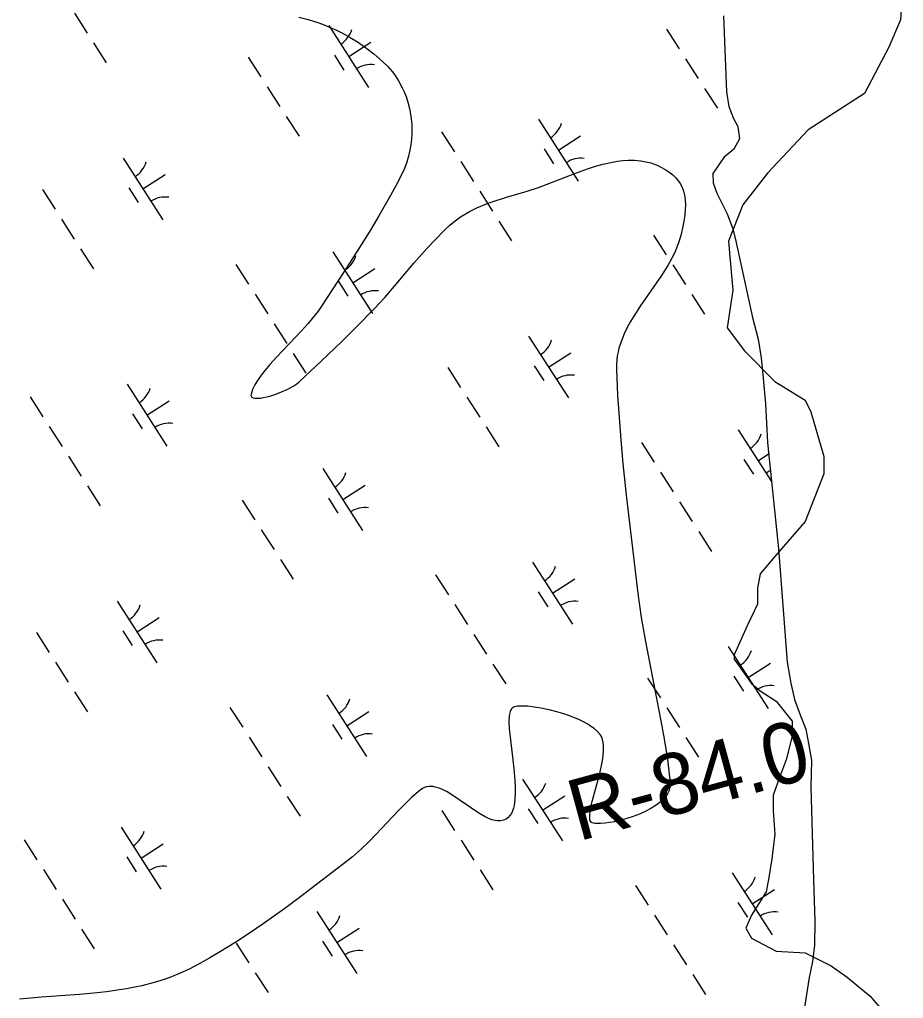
# Model space of a CAD drawing. Extents: x 3937982 to 3958556, y 219448 to 241894.
# Drawn here: x 3947210 to 3947811, y 231382 to 232047 of the extents above; entities that cross this region are included whole.
import ezdxf

# ---------------------------------------------------------------- set-up
doc = ezdxf.new("R2010")
doc.units = 0
for name, color, linetype in [('V-RIVR-EDGE', 7, 'Continuous'), ('V-RIVR-RANG-IDEN', 7, 'Continuous'), ('V-SITE-VEGE', 7, 'Continuous'), ('V-WETL-SWMP', 7, 'Continuous')]:
    doc.layers.add(name, color=color, linetype=linetype)

msp = doc.modelspace()

# ---------------------------------------------------------------- linework, layer by layer
at = {"layer": 'V-RIVR-EDGE'}
msp.add_lwpolyline([(3947811.4, 232077.583), (3947809.434, 232047.114), (3947801.571, 232028.439), (3947784.862, 231996.986), (3947746.529, 231972.413), (3947732.768, 231957.67), (3947719.008, 231942.927), (3947702.298, 231921.303), (3947692.469, 231896.73), (3947693.452, 231885.919), (3947695.418, 231863.312), (3947691.486, 231837.757), (3947703.281, 231822.03), (3947723.922, 231801.39), (3947744.563, 231788.612), (3947748.494, 231780.749), (3947757.34, 231750.279), (3947757.34, 231738.484), (3947744.563, 231706.049), (3947723.922, 231682.459), (3947714.093, 231670.664), (3947712.127, 231660.835), (3947712.127, 231650.024), (3947705.247, 231635.28), (3947696.401, 231615.622), (3947696.401, 231612.674), (3947708.196, 231595.964), (3947714.093, 231591.05), (3947724.905, 231584.17), (3947735.717, 231570.409), (3947735.717, 231560.58), (3947731.785, 231544.854), (3947727.854, 231534.042), (3947722.939, 231520.281), (3947722.939, 231509.47), (3947723.922, 231493.743), (3947721.956, 231477.034), (3947719.99, 231464.256), (3947718.025, 231454.427), (3947708.196, 231438.701), (3947704.264, 231429.855), (3947708.196, 231422.975), (3947724.905, 231414.129), (3947744.563, 231413.146), (3947762.255, 231404.3), (3947773.067, 231396.436), (3947788.793, 231383.659), (3947800.588, 231369.898)], dxfattribs=at)
at = {"layer": 'V-SITE-VEGE'}
for points in [[(3947400.382, 232048.852), (3947406.686, 232047.191), (3947413.833, 232044.926), (3947417.62, 232043.541), (3947421.638, 232041.921), (3947425.904, 232040.017), (3947430.428, 232037.776), (3947435.225, 232035.132), (3947440.306, 232032.005), (3947445.688, 232028.304), (3947451.381, 232023.913), (3947457.304, 232018.783), (3947460.778, 232015.33), (3947463.897, 232011.689), (3947465.777, 232009.17), (3947468.046, 232005.706), (3947470.655, 232000.928), (3947471.939, 231998.129), (3947473.225, 231994.873), (3947474.462, 231991.096), (3947475.581, 231986.721), (3947476.484, 231981.673), (3947477.039, 231975.877), (3947477.135, 231972.791), (3947477.086, 231969.512), (3947476.869, 231966.041), (3947476.453, 231962.377), (3947475.802, 231958.531), (3947474.882, 231954.511), (3947473.657, 231950.343), (3947472.074, 231946.054), (3947470.092, 231941.692), (3947466.479, 231934.684), (3947462.715, 231927.698), (3947454.787, 231913.786), (3947449.254, 231904.552), (3947441.641, 231892.28), (3947431.211, 231875.98), (3947415.371, 231851.74), (3947413.491, 231849.157), (3947409.399, 231843.994), (3947406.471, 231840.564), (3947402.387, 231836.011), (3947385.114, 231817.768), (3947380.674, 231812.875), (3947376.277, 231807.642), (3947374.141, 231804.845), (3947372.128, 231801.932), (3947370.32, 231798.91), (3947368.827, 231795.793), (3947368.249, 231794.23), (3947367.796, 231792.649), (3947367.745, 231791.703), (3947368.063, 231790.963), (3947368.464, 231790.582), (3947369.22, 231790.204), (3947370.576, 231789.921), (3947371.511, 231789.862), (3947374.223, 231790.03), (3947376.121, 231790.324), (3947378.462, 231790.824), (3947381.305, 231791.586), (3947384.674, 231792.676), (3947388.549, 231794.156), (3947392.8, 231796.098), (3947394.908, 231797.21), (3947396.98, 231798.437), (3947398.938, 231799.774), (3947400.677, 231801.216), (3947415.23, 231814.894), (3947429.732, 231828.772), (3947439.294, 231838.162), (3947451.826, 231850.896), (3947458.773, 231858.406), (3947465.463, 231866.082), (3947478.595, 231881.62), (3947487.586, 231891.895), (3947492.954, 231897.652), (3947499.384, 231904.083), (3947502.971, 231907.429), (3947506.548, 231910.438), (3947510.294, 231913.137), (3947512.877, 231914.779), (3947516.409, 231916.795), (3947521.267, 231919.201), (3947527.954, 231921.992), (3947531.86, 231923.418), (3947541.579, 231926.543)], [(3947541.579, 231926.543), (3947555.471, 231930.643), (3947563.249, 231933.127), (3947569.209, 231935.272), (3947587.926, 231942.597), (3947596.507, 231945.737), (3947601.444, 231947.351), (3947607.099, 231948.967), (3947613.548, 231950.425), (3947616.981, 231950.998), (3947620.62, 231951.43), (3947624.48, 231951.666), (3947628.562, 231951.633), (3947632.871, 231951.246), (3947637.403, 231950.396), (3947639.713, 231949.765), (3947642.075, 231948.973), (3947644.487, 231947.992), (3947646.947, 231946.802), (3947649.452, 231945.374), (3947651.997, 231943.683), (3947654.584, 231941.692), (3947656.743, 231939.654), (3947658.539, 231937.44), (3947659.544, 231935.88), (3947660.664, 231933.703), (3947661.797, 231930.651), (3947662.272, 231928.847), (3947662.676, 231926.742), (3947662.968, 231924.284), (3947663.106, 231921.435), (3947663.038, 231918.15), (3947662.719, 231914.4), (3947662.108, 231910.177), (3947661.201, 231905.529), (3947660.062, 231900.576), (3947658.797, 231896.196), (3947657.156, 231891.854), (3947655.878, 231888.979), (3947653.97, 231885.167), (3947651.117, 231880.115), (3947646.883, 231873.412), (3947632.48, 231852.563), (3947628.025, 231845.67), (3947625.82, 231841.959), (3947623.637, 231837.967), (3947621.546, 231833.668), (3947619.627, 231829.034), (3947617.996, 231824.018), (3947617.341, 231821.399), (3947616.813, 231818.673), (3947616.432, 231815.832), (3947616.225, 231812.871), (3947616.225, 231809.78), (3947617.06, 231791.815), (3947618.257, 231773.783), (3947619.227, 231761.728), (3947620.704, 231745.631), (3947622.934, 231724.135), (3947626.227, 231695.461), (3947630.837, 231657.313), (3947631.906, 231649.144), (3947633.127, 231640.99), (3947635.931, 231624.715), (3947637.991, 231613.887), (3947646.544, 231570.707), (3947648.739, 231558.395), (3947650.912, 231544.329), (3947651.887, 231536.827), (3947652.757, 231528.826), (3947652.759, 231526.569), (3947652.343, 231524.388), (3947651.848, 231522.981), (3947650.939, 231521.16), (3947649.312, 231518.837), (3947648.192, 231517.564), (3947646.754, 231516.159), (3947644.928, 231514.619), (3947642.626, 231512.952), (3947639.752, 231511.157), (3947636.215, 231509.271), (3947631.933, 231507.33), (3947626.86, 231505.403), (3947621.027, 231503.592), (3947614.838, 231502.105), (3947611.65, 231501.522), (3947608.5, 231501.089), (3947605.5, 231500.85), (3947602.831, 231500.85), (3947601.66, 231500.954), (3947600.633, 231501.143), (3947599.784, 231501.415), (3947599.034, 231501.95), (3947598.51, 231502.787), (3947598.278, 231503.504), (3947598.106, 231504.645), (3947598.096, 231506.47), (3947598.385, 231509.13), (3947599.171, 231513.212), (3947599.831, 231515.98), (3947604.631, 231533.941)], [(3947604.631, 231533.941), (3947606.11, 231540.37), (3947606.734, 231543.702), (3947607.226, 231547.126), (3947607.515, 231550.588), (3947607.498, 231554), (3947607.341, 231555.628), (3947607.06, 231557.199), (3947606.636, 231558.696), (3947606.046, 231560.094), (3947605.264, 231561.374), (3947603.452, 231563.453), (3947601.168, 231565.45), (3947599.413, 231566.73), (3947596.816, 231568.372), (3947592.96, 231570.437), (3947590.586, 231571.549), (3947584.397, 231574.043), (3947580.438, 231575.397), (3947575.84, 231576.779), (3947570.593, 231578.127), (3947564.771, 231579.346), (3947561.803, 231579.847), (3947555.79, 231580.568), (3947552.878, 231580.726), (3947548.938, 231580.605), (3947546.81, 231580.218), (3947545.798, 231579.733), (3947544.969, 231578.924), (3947544.516, 231578.211), (3947544.025, 231577.062), (3947543.562, 231575.203), (3947543.384, 231573.98), (3947543.187, 231570.539), (3947543.369, 231565.229), (3947543.67, 231561.614), (3947546.46, 231538.275), (3947547.203, 231530.052), (3947547.416, 231525.84), (3947547.455, 231521.555), (3947547.234, 231517.293), (3947546.654, 231513.246), (3947546.189, 231511.329), (3947545.581, 231509.513), (3947544.809, 231507.827), (3947543.847, 231506.306), (3947542.663, 231504.989), (3947541.227, 231503.912), (3947539.507, 231503.127), (3947537.428, 231502.703), (3947535.237, 231502.72), (3947533.721, 231502.957), (3947531.628, 231503.523), (3947528.736, 231504.671), (3947527.037, 231505.503), (3947522.756, 231507.975), (3947503.687, 231520.933), (3947501.183, 231522.391), (3947498.555, 231523.738), (3947495.815, 231524.887), (3947492.974, 231525.725), (3947491.551, 231525.975), (3947490.111, 231526.091), (3947488.659, 231526.051), (3947487.207, 231525.823), (3947485.755, 231525.379), (3947484.309, 231524.678), (3947482.878, 231523.687), (3947477.172, 231518.739), (3947471.616, 231513.4), (3947467.968, 231509.681), (3947456.716, 231497.702), (3947448.019, 231488.648), (3947442.907, 231483.694), (3947436.875, 231478.369), (3947433.558, 231475.719), (3947401.57, 231451.249), (3947390.695, 231443.182), (3947375.972, 231432.662), (3947367.426, 231426.823), (3947357.522, 231420.345), (3947346.008, 231413.251), (3947339.776, 231409.62), (3947333.05, 231405.88), (3947325.786, 231402.052), (3947319.222, 231398.95), (3947312.523, 231396.252), (3947307.985, 231394.663), (3947301.855, 231392.785), (3947293.554, 231390.667), (3947288.752, 231389.635), (3947283.216, 231388.597), (3947276.836, 231387.575), (3947269.484, 231386.592), (3947261.02, 231385.664), (3947251.288, 231384.796), (3947225.229, 231382.871), (3947210.426, 231381.58)]]:
    msp.add_lwpolyline(points, dxfattribs=at)
at = {"layer": 'V-WETL-SWMP'}
for p, q in [((3947247.67, 232051.52), (3947256.33, 232038.066)), ((3947420.684, 232043.177), (3947447.746, 232001.134)), ((3947650.242, 232040.741), (3947658.902, 232027.287)), ((3947260.66, 232031.339), (3947269.32, 232017.885)), ((3947434.215, 232022.156), (3947449.351, 232031.898)), ((3947424.48, 232023.025), (3947430.975, 232012.935)), ((3947365.818, 232021.78), (3947374.478, 232008.327)), ((3947663.232, 232020.56), (3947671.892, 232007.107)), ((3947378.808, 232001.6), (3947387.468, 231988.146)), ((3947676.222, 232000.38), (3947684.882, 231986.926)), ((3947391.798, 231981.419), (3947400.458, 231967.965)), ((3947563.25, 231979.487), (3947590.312, 231937.444)), ((3947497.385, 231970.892), (3947506.045, 231957.439)), ((3947576.781, 231958.466), (3947591.917, 231968.208)), ((3947567.046, 231959.335), (3947573.541, 231949.245)), ((3947280.817, 231953.148), (3947307.879, 231911.105)), ((3947510.375, 231950.712), (3947519.035, 231937.258)), ((3947294.348, 231932.126), (3947309.484, 231941.869)), ((3947225.951, 231931.751), (3947234.611, 231918.297)), ((3947284.613, 231932.996), (3947291.108, 231922.905)), ((3947523.365, 231930.531), (3947532.025, 231917.077)), ((3947238.941, 231911.57), (3947247.601, 231898.116)), ((3947536.355, 231910.35), (3947545.015, 231896.896)), ((3947641.513, 231900.792), (3947650.173, 231887.338)), ((3947251.931, 231891.389), (3947260.591, 231877.936)), ((3947423.383, 231889.458), (3947450.445, 231847.415)), ((3947357.518, 231880.863), (3947366.178, 231867.409)), ((3947436.914, 231868.436), (3947452.049, 231878.179)), ((3947654.503, 231880.611), (3947663.163, 231867.157)), ((3947427.179, 231869.305), (3947433.674, 231859.215)), ((3947370.508, 231860.682), (3947379.168, 231847.228)), ((3947667.493, 231860.43), (3947676.153, 231846.976)), ((3947383.498, 231840.501), (3947392.157, 231827.048)), ((3947556.512, 231832.159), (3947583.574, 231790.116)), ((3947396.487, 231820.321), (3947405.147, 231806.867)), ((3947570.043, 231811.138), (3947585.179, 231820.88)), ((3947501.646, 231810.762), (3947510.306, 231797.308)), ((3947560.308, 231812.007), (3947566.803, 231801.916)), ((3947283.515, 231799.428), (3947310.578, 231757.385)), ((3947217.65, 231790.833), (3947226.31, 231777.38)), ((3947514.636, 231790.581), (3947523.296, 231777.128)), ((3947297.047, 231778.407), (3947312.182, 231788.149)), ((3947287.311, 231779.276), (3947293.806, 231769.186)), ((3947230.64, 231770.653), (3947239.3, 231757.199)), ((3947527.626, 231770.401), (3947536.286, 231756.947)), ((3947699.078, 231768.469), (3947721.693, 231733.335)), ((3947633.213, 231759.874), (3947641.873, 231746.42)), ((3947243.63, 231750.472), (3947252.29, 231737.018)), ((3947712.609, 231747.447), (3947719.751, 231752.045)), ((3947702.874, 231748.317), (3947709.369, 231738.226)), ((3947416.645, 231742.13), (3947443.707, 231700.087)), ((3947646.203, 231739.693), (3947654.863, 231726.24)), ((3947256.62, 231730.291), (3947265.28, 231716.837)), ((3947430.176, 231721.108), (3947445.311, 231730.851)), ((3947361.779, 231720.733), (3947370.439, 231707.279)), ((3947420.441, 231721.977), (3947426.936, 231711.887)), ((3947659.193, 231719.513), (3947667.853, 231706.059)), ((3947374.769, 231700.552), (3947383.428, 231687.098)), ((3947672.183, 231699.332), (3947680.842, 231685.878)), ((3947387.758, 231680.371), (3947396.418, 231666.917)), ((3947559.211, 231678.44), (3947586.273, 231636.396)), ((3947493.346, 231669.845), (3947502.005, 231656.391)), ((3947572.742, 231657.418), (3947587.877, 231667.16)), ((3947563.007, 231658.287), (3947569.501, 231648.197)), ((3947276.777, 231652.1), (3947303.84, 231610.057)), ((3947506.335, 231649.664), (3947514.995, 231636.21)), ((3947290.309, 231631.079), (3947305.444, 231640.821)), ((3947221.911, 231630.703), (3947230.571, 231617.249)), ((3947280.573, 231631.948), (3947287.068, 231621.857)), ((3947519.325, 231629.483), (3947527.985, 231616.029)), ((3947692.34, 231621.141), (3947719.402, 231579.098)), ((3947234.901, 231610.522), (3947243.561, 231597.069)), ((3947532.315, 231609.302), (3947540.975, 231595.849)), ((3947705.871, 231600.119), (3947721.007, 231609.862)), ((3947637.474, 231599.744), (3947646.134, 231586.29)), ((3947696.136, 231600.989), (3947702.631, 231590.898)), ((3947247.891, 231590.342), (3947256.551, 231576.888)), ((3947419.343, 231588.41), (3947446.406, 231546.367)), ((3947353.478, 231579.815), (3947362.138, 231566.361)), ((3947432.874, 231567.388), (3947448.01, 231577.131)), ((3947650.464, 231579.563), (3947659.124, 231566.109)), ((3947423.139, 231568.258), (3947429.634, 231558.167)), ((3947366.468, 231559.634), (3947375.128, 231546.181)), ((3947663.454, 231559.382), (3947672.113, 231545.929)), ((3947379.458, 231539.454), (3947388.118, 231526)), ((3947552.473, 231531.111), (3947579.535, 231489.068)), ((3947392.448, 231519.273), (3947401.108, 231505.819)), ((3947566.004, 231510.09), (3947581.139, 231519.832)), ((3947556.269, 231510.959), (3947562.763, 231500.869)), ((3947497.606, 231509.714), (3947506.266, 231496.261)), ((3947279.476, 231498.381), (3947306.538, 231456.337)), ((3947213.611, 231489.786), (3947222.271, 231476.332)), ((3947293.007, 231477.359), (3947308.143, 231487.101)), ((3947510.596, 231489.534), (3947519.256, 231476.08)), ((3947283.272, 231478.228), (3947289.767, 231468.138)), ((3947226.601, 231469.605), (3947235.261, 231456.151)), ((3947523.586, 231469.353), (3947532.246, 231455.899)), ((3947695.038, 231467.421), (3947722.101, 231425.378)), ((3947629.173, 231458.826), (3947637.833, 231445.373)), ((3947708.57, 231446.4), (3947723.705, 231456.142)), ((3947239.591, 231449.424), (3947248.251, 231435.97)), ((3947698.834, 231447.269), (3947705.329, 231437.179)), ((3947412.605, 231441.082), (3947439.668, 231399.039)), ((3947642.163, 231438.646), (3947650.823, 231425.192)), ((3947252.581, 231429.243), (3947261.241, 231415.79)), ((3947426.136, 231420.06), (3947441.272, 231429.803)), ((3947357.739, 231419.685), (3947366.399, 231406.231)), ((3947416.401, 231420.93), (3947422.896, 231410.839)), ((3947655.153, 231418.465), (3947663.813, 231405.011)), ((3947370.729, 231399.504), (3947379.389, 231386.05)), ((3947668.143, 231398.284), (3947676.803, 231384.83))]:
    msp.add_line(p, q, dxfattribs=at)
msp.add_lwpolyline([(3947688.976, 232049.877), (3947691.131, 231998.159), (3947692.631, 231988.152), (3947695.743, 231980.027), (3947698.829, 231974.465), (3947699.846, 231966.085), (3947696.188, 231959.056), (3947689.254, 231953.392), (3947681.905, 231942.597), (3947681.969, 231936.305), (3947684.603, 231929.34), (3947686.985, 231924.237), (3947691.505, 231915.193), (3947695.097, 231905.674), (3947697.275, 231897.772), (3947708.765, 231844.75), (3947712.643, 231830.107), (3947714.637, 231817.308), (3947715.941, 231803.571), (3947717.516, 231786.107), (3947718.948, 231759.786), (3947726.437, 231687.613), (3947732.345, 231610.53), (3947734.819, 231596.338), (3947737.263, 231585.176), (3947741.098, 231574.727), (3947744.925, 231564.977), (3947746.889, 231555.208), (3947748.868, 231543.808), (3947748.353, 231525.625), (3947750.155, 231462.716), (3947751.14, 231434.526), (3947750.841, 231417.976), (3947749.552, 231407.242), (3947747.332, 231396.265), (3947743.604, 231373.155)], dxfattribs=at)
for centre, start, end in [((3947419.465, 232045.51), 301.99668, 343.540338), ((3947449.365, 231999.058), 81.996677, 123.540335), ((3947562.031, 231981.82), 301.99668, 343.540338), ((3947279.598, 231955.481), 301.99668, 343.540338), ((3947591.931, 231935.368), 81.996677, 123.540335), ((3947309.498, 231909.029), 81.996677, 123.540335), ((3947422.163, 231891.791), 301.99668, 343.540338), ((3947452.063, 231845.339), 81.996677, 123.540335), ((3947555.293, 231834.492), 301.99668, 343.540338), ((3947585.193, 231788.04), 81.996677, 123.540335), ((3947282.296, 231801.761), 301.99668, 343.540338), ((3947312.196, 231755.309), 81.996677, 123.540335), ((3947697.859, 231770.802), 301.99668, 343.540338), ((3947415.425, 231744.463), 301.99668, 343.540338), ((3947727.759, 231724.35), 112.766676, 123.540335), ((3947445.325, 231698.011), 81.996677, 123.540335), ((3947557.991, 231680.772), 301.99668, 343.540338), ((3947587.891, 231634.321), 81.996677, 123.540335), ((3947275.558, 231654.433), 301.99668, 343.540338), ((3947305.458, 231607.981), 81.996677, 123.540335), ((3947691.121, 231623.474), 301.99668, 343.540338), ((3947721.021, 231577.022), 81.996677, 123.540335), ((3947418.124, 231590.743), 301.99668, 343.540338), ((3947448.024, 231544.291), 81.996677, 123.540335), ((3947551.253, 231533.444), 301.99668, 343.540338), ((3947581.153, 231486.992), 81.996677, 123.540335), ((3947278.257, 231500.713), 301.99668, 343.540338), ((3947308.157, 231454.262), 81.996677, 123.540335), ((3947693.819, 231469.754), 301.99668, 343.540338), ((3947411.386, 231443.415), 301.99668, 343.540338), ((3947723.719, 231423.302), 81.996677, 123.540335), ((3947441.286, 231396.963), 81.996677, 123.540335)]:
    msp.add_arc(centre, 17.623, start, end, dxfattribs=at)

# ---------------------------------------------------------------- texts
at = {"layer": 'V-RIVR-RANG-IDEN'}
msp.add_text('R-84.0', height=41.5, rotation=15.281383, dxfattribs=at).set_placement((3947590.288, 231488.721))

doc.saveas('drawing.dxf')
